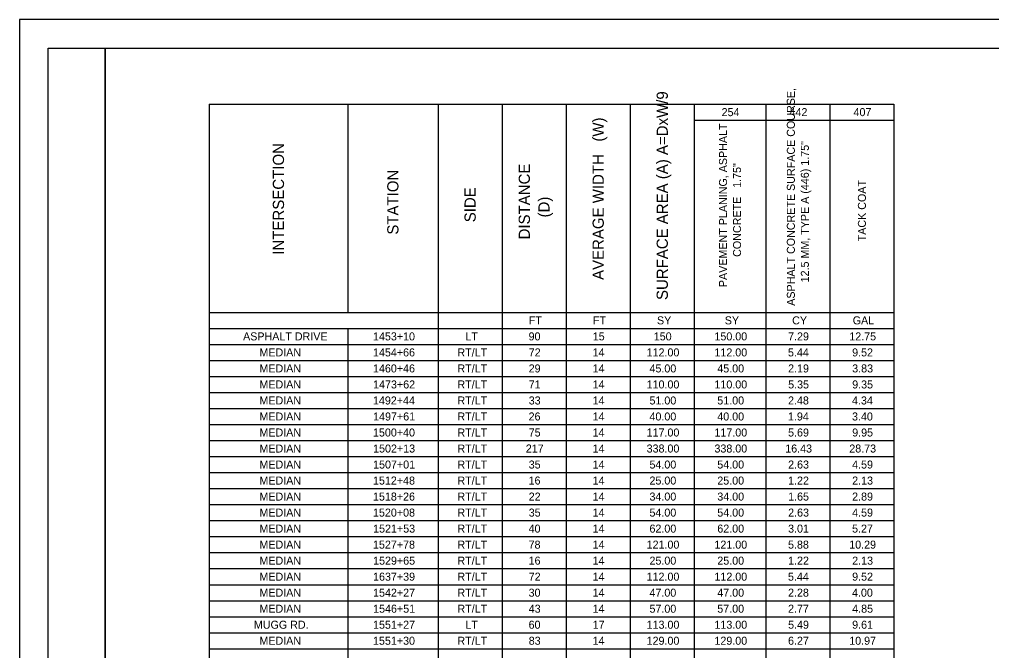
# Model space of a CAD drawing. Extents: x 0 to 34, y 0 to 22.
# Drawn here: x 0 to 17, y 10.97 to 22 of the extents above; entities that cross this region are included whole.
import ezdxf

# ---------------------------------------------------------------- set-up
doc = ezdxf.new("R2010")
doc.units = 0
for name, color, linetype in [('Default', 7, 'Continuous'), ('SH_Border', 7, 'Continuous'), ('SH_Cut_Line', 7, 'Continuous'), ('SH_Data', 7, 'Continuous')]:
    doc.layers.add(name, color=color, linetype=linetype)

msp = doc.modelspace()

# ---------------------------------------------------------------- linework, layer by layer
at = {"layer": 'SH_Border'}
for points in [[(0.5, 21.5), (1.5, 21.5), (1.5, 0.5), (0.5, 0.5)], [(1.5, 21.5), (33.5, 21.5), (33.5, 0.5), (1.5, 0.5)]]:
    msp.add_lwpolyline(points, close=True, dxfattribs=at)
at = {"layer": 'SH_Cut_Line'}
msp.add_lwpolyline([(0, 0), (34, 0), (34, 22), (0, 22)], close=True, dxfattribs=at)
at = {"layer": 'SH_Data'}
for p, q in [((3.319, 20.52), (15.293, 20.52)), ((3.319, 20.52), (3.319, 1.76)), ((5.74, 20.52), (5.74, 16.88)), ((7.321, 20.52), (7.321, 2.32)), ((8.441, 20.52), (8.441, 2.32)), ((9.561, 20.52), (9.561, 2.32)), ((10.681, 20.52), (10.681, 2.32)), ((11.801, 20.52), (11.801, 20.24)), ((13.053, 20.52), (13.053, 1.76)), ((14.173, 20.52), (14.173, 1.76)), ((15.293, 20.52), (15.293, 1.76)), ((11.801, 20.24), (15.293, 20.24)), ((11.801, 20.24), (11.801, 1.76)), ((3.319, 16.88), (15.293, 16.88)), ((3.319, 16.6), (15.293, 16.6)), ((5.74, 16.6), (5.74, 2.32)), ((3.319, 16.32), (15.293, 16.32)), ((3.319, 16.04), (15.293, 16.04)), ((3.319, 15.76), (15.293, 15.76)), ((3.319, 15.48), (15.293, 15.48)), ((3.319, 15.2), (15.293, 15.2)), ((3.319, 14.92), (15.293, 14.92)), ((3.319, 14.64), (15.293, 14.64)), ((3.319, 14.36), (15.293, 14.36)), ((3.319, 14.08), (15.293, 14.08)), ((3.319, 13.8), (15.293, 13.8)), ((3.319, 13.52), (15.293, 13.52)), ((3.319, 13.24), (15.293, 13.24)), ((3.319, 12.96), (15.293, 12.96)), ((3.319, 12.68), (15.293, 12.68)), ((3.319, 12.4), (15.293, 12.4)), ((3.319, 12.12), (15.293, 12.12)), ((3.319, 11.84), (15.293, 11.84)), ((3.319, 11.56), (15.293, 11.56)), ((3.319, 11.28), (15.293, 11.28)), ((3.319, 11), (15.293, 11))]:
    msp.add_line(p, q, dxfattribs=at)

# ---------------------------------------------------------------- texts
at = {"layer": 'Default'}
for s, height, p in [('ASPHALT CONCRETE SURFACE COURSE, ', 0.14, (13.56, 16.995)), ('SURFACE AREA (A) A=DxW/9', 0.196, (11.339, 17.096)), ('AVERAGE WIDTH   (W)', 0.196, (10.219, 17.447)), ('PAVEMENT PLANING, ASPHALT ', 0.14, (12.374, 17.321)), ('INTERSECTION', 0.196, (4.627, 17.888)), ('12.5 MM, TYPE A (446) 1.75"', 0.14, (13.805, 17.404)), ('DISTANCE                                                                                                        ', 0.196, (8.927, 18.155)), ('CONCRETE   1.75"', 0.14, (12.619, 17.85)), ('STATION', 0.196, (6.628, 18.238)), ('SIDE', 0.196, (7.979, 18.455)), ('TACK COAT', 0.14, (14.803, 18.122)), ('(D)', 0.196, (9.27, 18.539))]:
    msp.add_text(s, height=height, rotation=90, dxfattribs=at).set_placement(p)
for s, p in [('254', (12.279, 20.31)), ('442', (13.467, 20.31)), ('407', (14.586, 20.31)), ('FT', (8.908, 16.67)), ('FT', (10.028, 16.67)), ('SY', (11.149, 16.67)), ('SY', (12.335, 16.67)), ('CY', (13.513, 16.67)), ('GAL', (14.572, 16.67)), ('ASPHALT DRIVE', (3.911, 16.39)), ('1453+10', (6.183, 16.39)), ('LT', (7.799, 16.39)), ('90', (8.904, 16.39)), ('15', (10.026, 16.39)), ('150', (11.093, 16.39)), ('150.00', (12.154, 16.39)), ('7.29', (13.442, 16.39)), ('12.75', (14.512, 16.39)), ('MEDIAN', (4.197, 16.11)), ('1454+66', (6.183, 16.11)), ('RT/LT', (7.659, 16.11)), ('72', (8.906, 16.11)), ('14', (10.023, 16.11)), ('112.00', (10.968, 16.11)), ('112.00', (12.154, 16.11)), ('5.44', (13.44, 16.11)), ('9.52', (14.562, 16.11)), ('MEDIAN', (4.197, 15.83)), ('1460+46', (6.183, 15.83)), ('RT/LT', (7.659, 15.83)), ('29', (8.905, 15.83)), ('14', (10.023, 15.83)), ('45.00', (11.018, 15.83)), ('45.00', (12.204, 15.83)), ('2.19', (13.442, 15.83)), ('3.83', (14.563, 15.83)), ('MEDIAN', (4.197, 15.55)), ('1473+62', (6.185, 15.55)), ('RT/LT', (7.659, 15.55)), ('71', (8.906, 15.55)), ('14', (10.023, 15.55)), ('110.00', (10.968, 15.55)), ('110.00', (12.154, 15.55)), ('5.35', (13.443, 15.55)), ('9.35', (14.563, 15.55)), ('MEDIAN', (4.197, 15.27)), ('1492+44', (6.182, 15.27)), ('RT/LT', (7.659, 15.27)), ('33', (8.906, 15.27)), ('14', (10.023, 15.27)), ('51.00', (11.018, 15.27)), ('51.00', (12.204, 15.27)), ('2.48', (13.441, 15.27)), ('4.34', (14.56, 15.27)), ('1497+61', (6.185, 14.99)), ('RT/LT', (7.659, 14.99)), ('26', (8.904, 14.99)), ('40.00', (11.018, 14.99)), ('40.00', (12.204, 14.99)), ('1.94', (13.44, 14.99)), ('3.40', (14.56, 14.99)), ('MEDIAN', (4.197, 14.99)), ('14', (10.023, 14.99)), ('MEDIAN', (4.197, 14.71)), ('1500+40', (6.183, 14.71)), ('RT/LT', (7.659, 14.71)), ('75', (8.906, 14.71)), ('14', (10.023, 14.71)), ('117.00', (10.968, 14.71)), ('117.00', (12.154, 14.71)), ('5.69', (13.442, 14.71)), ('9.95', (14.563, 14.71)), ('MEDIAN', (4.197, 14.43)), ('1502+13', (6.185, 14.43)), ('RT/LT', (7.659, 14.43)), ('217', (8.855, 14.43)), ('14', (10.023, 14.43)), ('338.00', (10.968, 14.43)), ('338.00', (12.154, 14.43)), ('16.43', (13.392, 14.43)), ('28.73', (14.512, 14.43)), ('MEDIAN', (4.197, 14.15)), ('1507+01', (6.185, 14.15)), ('RT/LT', (7.659, 14.15)), ('35', (8.906, 14.15)), ('14', (10.023, 14.15)), ('54.00', (11.018, 14.15)), ('54.00', (12.204, 14.15)), ('2.63', (13.443, 14.15)), ('4.59', (14.562, 14.15)), ('MEDIAN', (4.197, 13.87)), ('1512+48', (6.183, 13.87)), ('RT/LT', (7.659, 13.87)), ('16', (8.904, 13.87)), ('14', (10.023, 13.87)), ('25.00', (11.018, 13.87)), ('25.00', (12.204, 13.87)), ('1.22', (13.442, 13.87)), ('2.13', (14.563, 13.87)), ('MEDIAN', (4.197, 13.59)), ('1518+26', (6.183, 13.59)), ('RT/LT', (7.659, 13.59)), ('22', (8.906, 13.59)), ('14', (10.023, 13.59)), ('34.00', (11.018, 13.59)), ('34.00', (12.204, 13.59)), ('1.65', (13.443, 13.59)), ('2.89', (14.562, 13.59)), ('MEDIAN', (4.197, 13.31)), ('1520+08', (6.183, 13.31)), ('RT/LT', (7.659, 13.31)), ('35', (8.906, 13.31)), ('14', (10.023, 13.31)), ('54.00', (11.018, 13.31)), ('54.00', (12.204, 13.31)), ('2.63', (13.443, 13.31)), ('4.59', (14.562, 13.31)), ('MEDIAN', (4.197, 13.03)), ('1521+53', (6.185, 13.03)), ('RT/LT', (7.659, 13.03)), ('40', (8.904, 13.03)), ('14', (10.023, 13.03)), ('62.00', (11.018, 13.03)), ('62.00', (12.204, 13.03)), ('3.01', (13.442, 13.03)), ('5.27', (14.561, 13.03)), ('MEDIAN', (4.197, 12.75)), ('1527+78', (6.183, 12.75)), ('RT/LT', (7.659, 12.75)), ('78', (8.904, 12.75)), ('14', (10.023, 12.75)), ('121.00', (10.968, 12.75)), ('121.00', (12.154, 12.75)), ('5.88', (13.441, 12.75)), ('10.29', (14.511, 12.75)), ('MEDIAN', (4.197, 12.47)), ('1529+65', (6.185, 12.47)), ('RT/LT', (7.659, 12.47)), ('16', (8.904, 12.47)), ('14', (10.023, 12.47)), ('25.00', (11.018, 12.47)), ('25.00', (12.204, 12.47)), ('1.22', (13.442, 12.47)), ('2.13', (14.563, 12.47)), ('MEDIAN', (4.197, 12.19)), ('1637+39', (6.184, 12.19)), ('RT/LT', (7.659, 12.19)), ('72', (8.906, 12.19)), ('14', (10.023, 12.19)), ('112.00', (10.968, 12.19)), ('112.00', (12.154, 12.19)), ('5.44', (13.44, 12.19)), ('9.52', (14.562, 12.19)), ('MEDIAN', (4.197, 11.91)), ('1542+27', (6.184, 11.91)), ('RT/LT', (7.659, 11.91)), ('30', (8.904, 11.91)), ('14', (10.023, 11.91)), ('47.00', (11.018, 11.91)), ('47.00', (12.204, 11.91)), ('2.28', (13.441, 11.91)), ('4.00', (14.56, 11.91)), ('MEDIAN', (4.197, 11.63)), ('1546+51', (6.185, 11.63)), ('RT/LT', (7.659, 11.63)), ('43', (8.906, 11.63)), ('14', (10.023, 11.63)), ('57.00', (11.018, 11.63)), ('57.00', (12.204, 11.63)), ('2.77', (13.441, 11.63)), ('4.85', (14.563, 11.63)), ('MUGG RD.', (4.1, 11.35)), ('1551+27', (6.184, 11.35)), ('LT', (7.799, 11.35)), ('60', (8.904, 11.35)), ('17', (10.025, 11.35)), ('113.00', (10.968, 11.35)), ('113.00', (12.154, 11.35)), ('5.49', (13.442, 11.35)), ('9.61', (14.562, 11.35)), ('MEDIAN', (4.197, 11.07)), ('1551+30', (6.183, 11.07)), ('RT/LT', (7.659, 11.07)), ('83', (8.906, 11.07)), ('14', (10.023, 11.07)), ('129.00', (10.968, 11.07)), ('129.00', (12.154, 11.07)), ('6.27', (13.441, 11.07)), ('10.97', (14.511, 11.07))]:
    msp.add_text(s, height=0.14, dxfattribs=at).set_placement(p)

doc.saveas('drawing.dxf')
